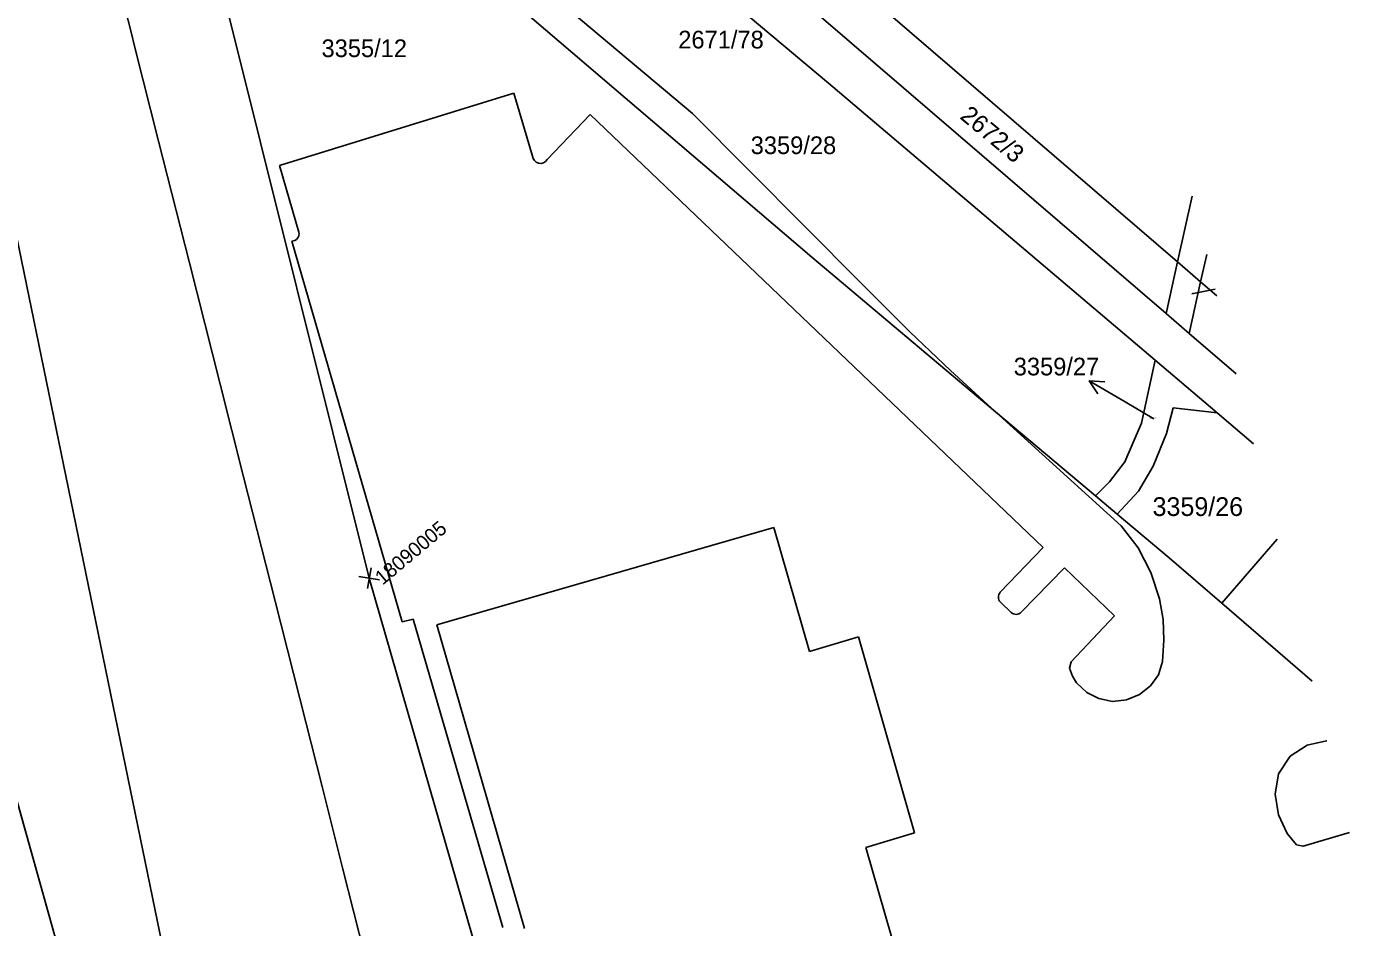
# Model space of a CAD drawing. Extents: x -754679 to -754173, y -1169241 to -1168288.
# Drawn here: x -754507.9 to -754412.5, y -1168566.4 to -1168501.5 of the extents above; entities that cross this region are included whole.
import ezdxf

# ---------------------------------------------------------------- set-up
doc = ezdxf.new("R2010")
doc.units = 0
for name, color, linetype in [('Vrstva 1', 7, 'Continuous'), ('Vrstva 16', 7, 'Continuous'), ('Vrstva 18', 7, 'Continuous'), ('Vrstva 4', 7, 'Continuous'), ('Vrstva 52', 7, 'Continuous'), ('Vrstva 53', 7, 'Continuous'), ('Vrstva 60', 7, 'Continuous')]:
    doc.layers.add(name, color=color, linetype=linetype)

msp = doc.modelspace()

# ---------------------------------------------------------------- linework, layer by layer
at = {"layer": 'Vrstva 1'}
for p, q in [((-754519.8, -1168462.41), (-754486.32, -1168624.94)), ((-754493.82, -1168481.8), (-754451.31, -1168518.1)), ((-754450.1, -1168505.56), (-754474, -1168485.49)), ((-754425.77, -1168522.16), (-754459.22, -1168493.4)), ((-754494.84, -1168494.63), (-754483.21, -1168541.23)), ((-754424.94, -1168518.44), (-754447.92, -1168498.69)), ((-754426.56, -1168525.52), (-754450.1, -1168505.56)), ((-754472.79, -1168506.27), (-754489.67, -1168511.5)), ((-754471.44, -1168510.82), (-754472.79, -1168506.27)), ((-754467.28, -1168507.81), (-754470.39, -1168511.07)), ((-754434.63, -1168539.02), (-754467.28, -1168507.81)), ((-754489.67, -1168511.5), (-754488.29, -1168516.29)), ((-754424.94, -1168518.44), (-754423.885, -1168513.694)), ((-754488.79, -1168516.94), (-754480.84, -1168544.38)), ((-754451.31, -1168518.1), (-754438.06, -1168529.24)), ((-754422.844, -1168517.902), (-754423.28, -1168519.87)), ((-754424.94, -1168518.44), (-754425.77, -1168522.16)), ((-754423.28, -1168519.87), (-754424.94, -1168518.44)), ((-754423.28, -1168519.87), (-754424.11, -1168523.59)), ((-754422.109, -1168520.876), (-754423.28, -1168519.87)), ((-754424.11, -1168523.59), (-754425.77, -1168522.16)), ((-754420.717, -1168526.508), (-754424.11, -1168523.59)), ((-754426.56, -1168525.52), (-754427.55, -1168530.05)), ((-754422.09, -1168529.32), (-754426.56, -1168525.52)), ((-754438.06, -1168529.24), (-754429.01, -1168537.46)), ((-754438.06, -1168529.24), (-754430.86, -1168535.3)), ((-754425.25, -1168528.95), (-754425.75, -1168530.81)), ((-754422.09, -1168529.32), (-754425.25, -1168528.95)), ((-754419.472, -1168531.539), (-754422.09, -1168529.32)), ((-754427.55, -1168530.05), (-754428.74, -1168532.86)), ((-754425.75, -1168530.81), (-754426.71, -1168533.16)), ((-754428.74, -1168532.86), (-754429.84, -1168534.28)), ((-754426.71, -1168533.16), (-754427.75, -1168534.95)), ((-754502.42, -1168579.34), (-754515.13, -1168534.05)), ((-754429.84, -1168534.28), (-754430.86, -1168535.3)), ((-754430.86, -1168535.3), (-754429.3, -1168536.61)), ((-754427.75, -1168534.95), (-754429.3, -1168536.61)), ((-754429.3, -1168536.61), (-754425.54, -1168539.77)), ((-754478.33, -1168544.59), (-754454.05, -1168537.59)), ((-754454.05, -1168537.59), (-754451.48, -1168546.52)), ((-754429.01, -1168537.46), (-754427.79, -1168539.04)), ((-754437.72, -1168542.25), (-754434.63, -1168539.02)), ((-754427.79, -1168539.04), (-754426.86, -1168540.83)), ((-754417.772, -1168538.417), (-754421.76, -1168543.03)), ((-754425.54, -1168539.77), (-754421.76, -1168543.03)), ((-754433.1, -1168540.48), (-754436.22, -1168543.69)), ((-754429.48, -1168543.95), (-754433.1, -1168540.48)), ((-754426.86, -1168540.83), (-754426.25, -1168542.73)), ((-754483.21, -1168541.23), (-754460.6, -1168619.67)), ((-754436.93, -1168543.71), (-754437.7, -1168542.95)), ((-754426.25, -1168542.73), (-754425.99, -1168544.22)), ((-754421.76, -1168543.03), (-754415.241, -1168548.65)), ((-754432.61, -1168547.25), (-754429.48, -1168543.95)), ((-754480.84, -1168544.38), (-754480.05, -1168544.18)), ((-754480.05, -1168544.18), (-754473.59, -1168566.41)), ((-754472.02, -1168566.47), (-754478.33, -1168544.59)), ((-754425.99, -1168544.22), (-754425.93, -1168545.71)), ((-754451.48, -1168546.52), (-754447.94, -1168545.46)), ((-754447.94, -1168545.46), (-754443.9, -1168559.58)), ((-754425.93, -1168545.71), (-754426.04, -1168547.24)), ((-754432.73, -1168547.73), (-754432.61, -1168547.25)), ((-754432.51, -1168548.29), (-754432.73, -1168547.73)), ((-754426.04, -1168547.24), (-754426.32, -1168548.19)), ((-754432.22, -1168548.77), (-754432.51, -1168548.29)), ((-754431.49, -1168549.46), (-754432.22, -1168548.77)), ((-754426.32, -1168548.19), (-754426.9, -1168548.99)), ((-754430.61, -1168549.91), (-754431.49, -1168549.46)), ((-754427.68, -1168549.62), (-754428.62, -1168549.99)), ((-754426.9, -1168548.99), (-754427.68, -1168549.62)), ((-754429.64, -1168550.11), (-754430.61, -1168549.91)), ((-754428.62, -1168549.99), (-754429.64, -1168550.11)), ((-754416.82, -1168554.05), (-754415.6, -1168553.26)), ((-754415.6, -1168553.26), (-754414.2, -1168552.96)), ((-754414.2, -1168552.96), (-754414.175, -1168552.963)), ((-754417.66, -1168555.34), (-754416.82, -1168554.05)), ((-754417.9, -1168556.81), (-754417.66, -1168555.34)), ((-754417.67, -1168558.28), (-754417.9, -1168556.81)), ((-754417.03, -1168559.64), (-754417.67, -1168558.28)), ((-754443.9, -1168559.58), (-754447.41, -1168560.64)), ((-754416.38, -1168560.45), (-754417.03, -1168559.64)), ((-754412.546, -1168559.551), (-754415.9, -1168560.54)), ((-754447.41, -1168560.64), (-754434.1, -1168606.84)), ((-754415.9, -1168560.54), (-754416.38, -1168560.45))]:
    msp.add_line(p, q, dxfattribs=at)
for points in [[(-754498.393, -1168509.746), (-754500.095, -1168502.999), (-754500.372, -1168501.892), (-754500.594, -1168501.052), (-754502.803, -1168492.326), (-754502.981, -1168491.622), (-754505.012, -1168483.589), (-754507.469, -1168473.859), (-754508.579, -1168469.465), (-754510.811, -1168460.627), (-754513.137, -1168451.466)], [(-754478.966, -1168586.464), (-754480.559, -1168580.169), (-754482.76, -1168571.467), (-754485.127, -1168562.116), (-754486.611, -1168556.258), (-754487.789, -1168551.609), (-754490.001, -1168542.893), (-754492.27, -1168533.933), (-754493.964, -1168527.245), (-754496.176, -1168518.505), (-754498.393, -1168509.746)]]:
    msp.add_lwpolyline(points, dxfattribs=at)
for centre, radius, start, end in [((-754470.874, -1168510.774), 0.567, 184.62239, 328.59261), ((-754488.789, -1168516.423), 0.517, 269.93027, 14.93254), ((-754437.379, -1168542.591), 0.482, 135.02582, 228.24733), ((-754436.586, -1168543.323), 0.518, 228.30652, 314.92056)]:
    msp.add_arc(centre, radius, start, end, dxfattribs=at)
at = {"layer": 'Vrstva 16'}
for p, q in [((-754423.91, -1168520.73), (-754422.228, -1168520.397)), ((-754431.306, -1168527.009), (-754428.72, -1168528.53)), ((-754426.66, -1168529.74), (-754428.72, -1168528.53))]:
    msp.add_line(p, q, dxfattribs=at)
msp.add_lwpolyline([(-754430.697, -1168527.947), (-754431.306, -1168527.009), (-754430.19, -1168527.085)], dxfattribs=at)
at = {"layer": 'Vrstva 4'}
for p, q in [((-754459.9, -1168507.75), (-754493.21, -1168479.76)), ((-754447.78, -1168519.94), (-754459.9, -1168507.75)), ((-754444.25, -1168523.49), (-754447.78, -1168519.94)), ((-754441.31, -1168526.26), (-754444.25, -1168523.49)), ((-754438.06, -1168529.24), (-754441.31, -1168526.26))]:
    msp.add_line(p, q, dxfattribs=at)
at = {"layer": 'Vrstva 53'}
for p, q in [((-754494.84, -1168494.63), (-754483.21, -1168541.23)), ((-754490.14, -1168623.07), (-754523.85, -1168502.96)), ((-754483.21, -1168541.23), (-754460.6, -1168619.67))]:
    msp.add_line(p, q, dxfattribs=at)
at = {"layer": 'Vrstva 60'}
for p, q in [((-754483.949, -1168541.1), (-754482.471, -1168541.36)), ((-754483.08, -1168540.491), (-754483.34, -1168541.969))]:
    msp.add_line(p, q, dxfattribs=at)

# ---------------------------------------------------------------- texts
at = {"layer": 'Vrstva 16'}
for s, p in [('2671/78', (-754460.934, -1168503.055)), ('3359/27', (-754436.752, -1168526.62))]:
    msp.add_text(s, height=1.275, rotation=360, dxfattribs=at).set_placement(p)
at = {"layer": 'Vrstva 18'}
for s, rotation, p in [('3355/12', 360, (-754486.65, -1168503.68)), ('2672/3', 320.398, (-754440.701, -1168508.059)), ('3359/28', 360, (-754455.712, -1168510.67))]:
    msp.add_text(s, height=1.275, rotation=rotation, dxfattribs=at).set_placement(p)
for s, height, p in [('2672/2', 0.1, (-754423.896, -1168520.73)), ('3359/27', 0.1, (-754426.958, -1168529.74)), ('3359/26', 1.35, (-754426.745, -1168536.75))]:
    msp.add_text(s, height=height, dxfattribs=at).set_placement(p)
at = {"layer": 'Vrstva 52'}
msp.add_text(' 18090005', height=1.0368, rotation=40, dxfattribs=at).set_placement((-754482.544, -1168542.024))

doc.saveas('drawing.dxf')
